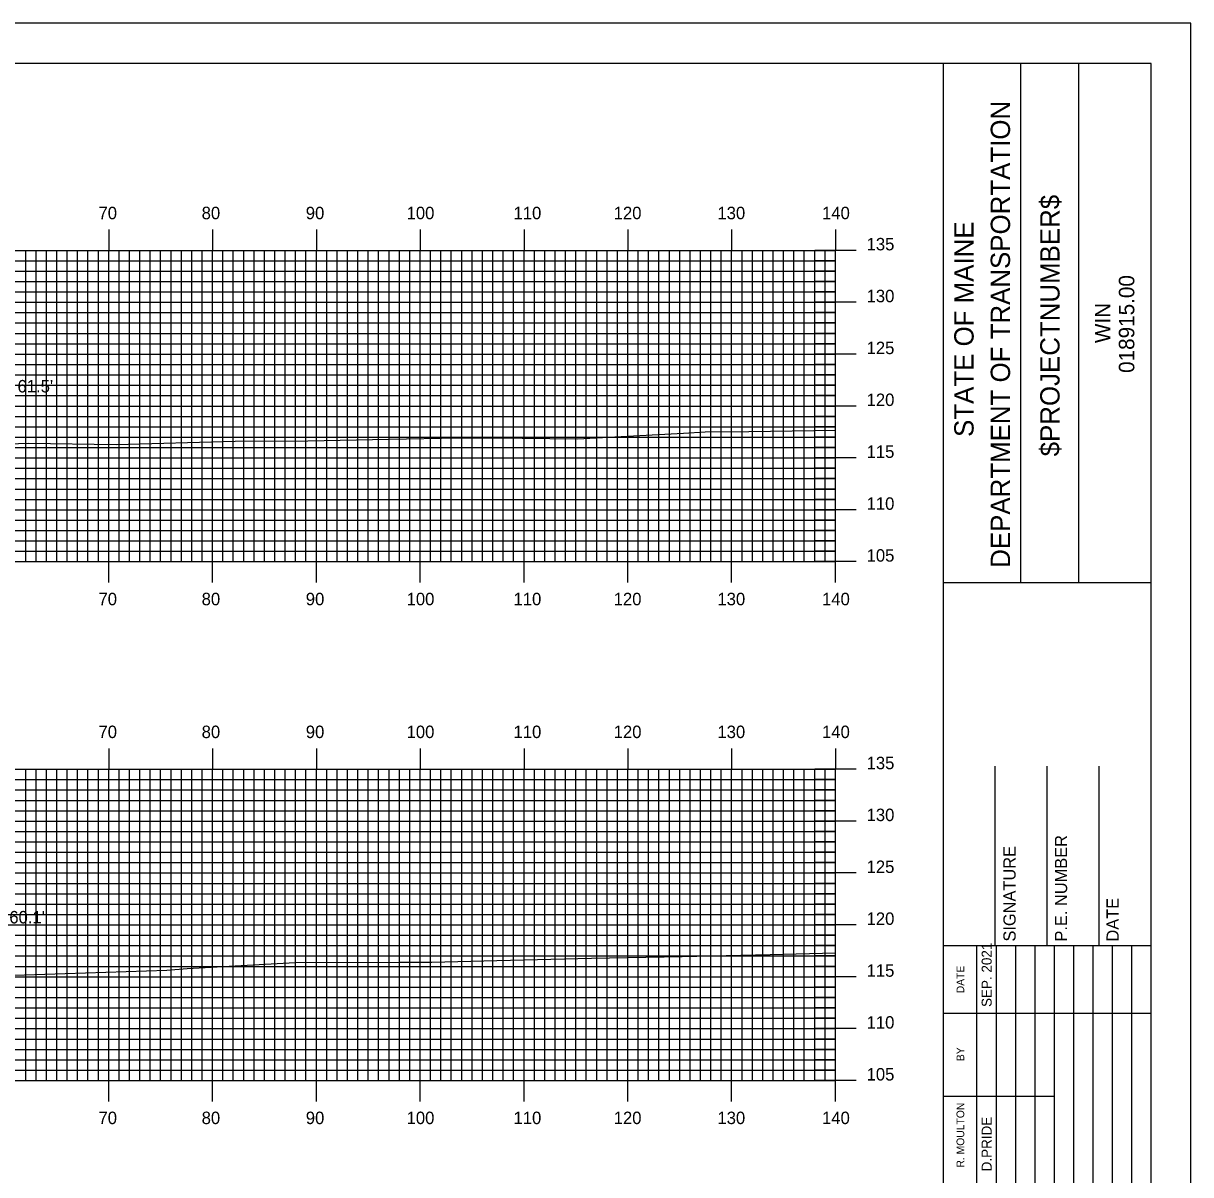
# Model space of a CAD drawing. Extents: x 1788550 to 1788893, y 442591 to 442811.
# Drawn here: x 1788777.4 to 1788889.9, y 442699.6 to 442810.5 of the extents above; entities that cross this region are included whole.
import ezdxf

# ---------------------------------------------------------------- set-up
doc = ezdxf.new("R2010")
doc.units = 0
for name, color, linetype in [('BORDER', 7, 'Continuous'), ('D_Text_Standard', 7, 'Continuous'), ('H_V ANNOTATION', 7, 'Continuous'), ('MAJOR', 7, 'Continuous'), ('MINOR', 7, 'Continuous'), ('PLOT BOUNDARY', 7, 'Continuous'), ('S_Roadway_Centerline', 7, 'Continuous')]:
    doc.layers.add(name, color=color, linetype=linetype)

msp = doc.modelspace()

# ---------------------------------------------------------------- linework, layer by layer
at = {"layer": 'BORDER'}
for p, q in [((1788866.04, 442596.67), (1788866.04, 442806.67)), ((1788873.5, 442756.66), (1788873.5, 442806.66)), ((1788879.09, 442756.66), (1788879.09, 442806.66)), ((1788866.05, 442756.65), (1788886.04, 442756.65)), ((1788871.04, 442721.67), (1788871.04, 442738.97)), ((1788876.04, 442721.67), (1788876.04, 442738.97)), ((1788881.04, 442721.67), (1788881.04, 442738.97)), ((1788866.04, 442721.67), (1788886.04, 442721.67))]:
    msp.add_line(p, q, dxfattribs=at)
msp.add_lwpolyline([(1788566.04, 442596.67), (1788886.04, 442596.67), (1788886.04, 442806.67), (1788566.04, 442806.67)], close=True, dxfattribs=at)
for points in [[(1788869.27, 442715.17), (1788869.27, 442721.67)], [(1788871.14, 442686.68), (1788871.14, 442721.67)], [(1788873, 442721.67), (1788873, 442686.68)], [(1788874.87, 442686.68), (1788874.87, 442721.67)], [(1788876.73, 442686.68), (1788876.73, 442721.67)], [(1788878.59, 442686.68), (1788878.59, 442721.67)], [(1788880.46, 442686.68), (1788880.46, 442721.67)], [(1788882.32, 442686.68), (1788882.32, 442721.67)], [(1788884.18, 442686.68), (1788884.18, 442721.67)], [(1788869.27, 442686.68), (1788869.27, 442720.26)], [(1788866.04, 442715.17), (1788886.04, 442715.17)], [(1788866.04, 442707.17), (1788869.27, 442707.17)], [(1788869.27, 442707.17), (1788876.73, 442707.17)]]:
    msp.add_lwpolyline(points, dxfattribs=at)
at = {"layer": 'MAJOR'}
for p, q in [((1788785.64, 442790.67), (1788785.64, 442788.67)), ((1788795.64, 442790.67), (1788795.64, 442788.67)), ((1788805.64, 442790.67), (1788805.64, 442788.67)), ((1788815.64, 442790.67), (1788815.64, 442788.67)), ((1788825.64, 442790.67), (1788825.64, 442788.67)), ((1788835.64, 442790.67), (1788835.64, 442788.67)), ((1788845.64, 442790.67), (1788845.64, 442788.67)), ((1788855.64, 442790.67), (1788855.64, 442788.67)), ((1788575.64, 442788.67), (1788855.64, 442788.67)), ((1788575.64, 442788.67), (1788855.64, 442788.67)), ((1788785.64, 442758.67), (1788785.64, 442788.67)), ((1788795.64, 442758.67), (1788795.64, 442788.67)), ((1788805.64, 442758.67), (1788805.64, 442788.67)), ((1788815.64, 442758.67), (1788815.64, 442788.67)), ((1788825.64, 442758.67), (1788825.64, 442788.67)), ((1788835.64, 442758.67), (1788835.64, 442788.67)), ((1788845.64, 442758.67), (1788845.64, 442788.67)), ((1788857.65, 442788.67), (1788853.64, 442788.67)), ((1788855.64, 442758.67), (1788855.64, 442788.67)), ((1788855.64, 442758.67), (1788855.64, 442788.67)), ((1788575.64, 442783.67), (1788855.64, 442783.67)), ((1788857.65, 442783.67), (1788853.64, 442783.67)), ((1788575.64, 442778.67), (1788855.64, 442778.67)), ((1788857.65, 442778.67), (1788853.64, 442778.67)), ((1788575.64, 442773.67), (1788855.64, 442773.67)), ((1788857.65, 442773.67), (1788853.64, 442773.67)), ((1788575.64, 442768.67), (1788855.64, 442768.67)), ((1788857.65, 442768.67), (1788853.64, 442768.67)), ((1788575.64, 442763.67), (1788855.64, 442763.67)), ((1788857.65, 442763.67), (1788853.64, 442763.67)), ((1788575.64, 442758.67), (1788855.64, 442758.67)), ((1788575.64, 442758.67), (1788855.64, 442758.67)), ((1788785.64, 442756.66), (1788785.64, 442758.67)), ((1788795.64, 442756.66), (1788795.64, 442758.67)), ((1788805.64, 442756.66), (1788805.64, 442758.67)), ((1788815.64, 442756.66), (1788815.64, 442758.67)), ((1788825.64, 442756.66), (1788825.64, 442758.67)), ((1788835.64, 442756.66), (1788835.64, 442758.67)), ((1788845.64, 442756.66), (1788845.64, 442758.67)), ((1788857.65, 442758.67), (1788853.64, 442758.67)), ((1788855.64, 442756.66), (1788855.64, 442758.67)), ((1788785.64, 442740.67), (1788785.64, 442738.67)), ((1788795.64, 442740.67), (1788795.64, 442738.67)), ((1788805.64, 442740.67), (1788805.64, 442738.67)), ((1788815.64, 442740.67), (1788815.64, 442738.67)), ((1788825.64, 442740.67), (1788825.64, 442738.67)), ((1788835.64, 442740.67), (1788835.64, 442738.67)), ((1788845.64, 442740.67), (1788845.64, 442738.67)), ((1788855.64, 442740.67), (1788855.64, 442738.67)), ((1788575.64, 442738.67), (1788855.64, 442738.67)), ((1788575.64, 442738.67), (1788855.64, 442738.67)), ((1788785.64, 442708.67), (1788785.64, 442738.67)), ((1788795.64, 442708.67), (1788795.64, 442738.67)), ((1788805.64, 442708.67), (1788805.64, 442738.67)), ((1788815.64, 442708.67), (1788815.64, 442738.67)), ((1788825.64, 442708.67), (1788825.64, 442738.67)), ((1788835.64, 442708.67), (1788835.64, 442738.67)), ((1788845.64, 442708.67), (1788845.64, 442738.67)), ((1788857.65, 442738.67), (1788853.64, 442738.67)), ((1788855.64, 442708.67), (1788855.64, 442738.67)), ((1788855.64, 442708.67), (1788855.64, 442738.67)), ((1788575.64, 442733.67), (1788855.64, 442733.67)), ((1788857.65, 442733.67), (1788853.64, 442733.67)), ((1788575.64, 442728.67), (1788855.64, 442728.67)), ((1788857.65, 442728.67), (1788853.64, 442728.67)), ((1788575.64, 442723.67), (1788855.64, 442723.67)), ((1788857.65, 442723.67), (1788853.64, 442723.67)), ((1788575.64, 442718.67), (1788855.64, 442718.67)), ((1788857.65, 442718.67), (1788853.64, 442718.67)), ((1788575.64, 442713.67), (1788855.64, 442713.67)), ((1788857.65, 442713.67), (1788853.64, 442713.67)), ((1788575.64, 442708.67), (1788855.64, 442708.67)), ((1788575.64, 442708.67), (1788855.64, 442708.67)), ((1788785.64, 442706.66), (1788785.64, 442708.67)), ((1788795.64, 442706.66), (1788795.64, 442708.67)), ((1788805.64, 442706.66), (1788805.64, 442708.67)), ((1788815.64, 442706.66), (1788815.64, 442708.67)), ((1788825.64, 442706.66), (1788825.64, 442708.67)), ((1788835.64, 442706.66), (1788835.64, 442708.67)), ((1788845.64, 442706.66), (1788845.64, 442708.67)), ((1788857.65, 442708.67), (1788853.64, 442708.67)), ((1788855.64, 442706.66), (1788855.64, 442708.67))]:
    msp.add_line(p, q, dxfattribs=at)
at = {"layer": 'MINOR'}
for p, q in [((1788777.64, 442758.67), (1788777.64, 442788.67)), ((1788778.64, 442758.67), (1788778.64, 442788.67)), ((1788779.64, 442758.67), (1788779.64, 442788.67)), ((1788780.64, 442758.67), (1788780.64, 442788.67)), ((1788781.64, 442758.67), (1788781.64, 442788.67)), ((1788782.64, 442758.67), (1788782.64, 442788.67)), ((1788783.64, 442758.67), (1788783.64, 442788.67)), ((1788784.64, 442758.67), (1788784.64, 442788.67)), ((1788786.64, 442758.67), (1788786.64, 442788.67)), ((1788787.64, 442758.67), (1788787.64, 442788.67)), ((1788788.64, 442758.67), (1788788.64, 442788.67)), ((1788789.64, 442758.67), (1788789.64, 442788.67)), ((1788790.64, 442758.67), (1788790.64, 442788.67)), ((1788791.64, 442758.67), (1788791.64, 442788.67)), ((1788792.64, 442758.67), (1788792.64, 442788.67)), ((1788793.64, 442758.67), (1788793.64, 442788.67)), ((1788794.64, 442758.67), (1788794.64, 442788.67)), ((1788796.64, 442758.67), (1788796.64, 442788.67)), ((1788797.64, 442758.67), (1788797.64, 442788.67)), ((1788798.64, 442758.67), (1788798.64, 442788.67)), ((1788799.64, 442758.67), (1788799.64, 442788.67)), ((1788800.64, 442758.67), (1788800.64, 442788.67)), ((1788801.64, 442758.67), (1788801.64, 442788.67)), ((1788802.64, 442758.67), (1788802.64, 442788.67)), ((1788803.64, 442758.67), (1788803.64, 442788.67)), ((1788804.64, 442758.67), (1788804.64, 442788.67)), ((1788806.64, 442758.67), (1788806.64, 442788.67)), ((1788807.64, 442758.67), (1788807.64, 442788.67)), ((1788808.64, 442758.67), (1788808.64, 442788.67)), ((1788809.64, 442758.67), (1788809.64, 442788.67)), ((1788810.64, 442758.67), (1788810.64, 442788.67)), ((1788811.64, 442758.67), (1788811.64, 442788.67)), ((1788812.64, 442758.67), (1788812.64, 442788.67)), ((1788813.64, 442758.67), (1788813.64, 442788.67)), ((1788814.64, 442758.67), (1788814.64, 442788.67)), ((1788816.64, 442758.67), (1788816.64, 442788.67)), ((1788817.64, 442758.67), (1788817.64, 442788.67)), ((1788818.64, 442758.67), (1788818.64, 442788.67)), ((1788819.64, 442758.67), (1788819.64, 442788.67)), ((1788820.64, 442758.67), (1788820.64, 442788.67)), ((1788821.64, 442758.67), (1788821.64, 442788.67)), ((1788822.64, 442758.67), (1788822.64, 442788.67)), ((1788823.64, 442758.67), (1788823.64, 442788.67)), ((1788824.64, 442758.67), (1788824.64, 442788.67)), ((1788826.64, 442758.67), (1788826.64, 442788.67)), ((1788827.64, 442758.67), (1788827.64, 442788.67)), ((1788828.64, 442758.67), (1788828.64, 442788.67)), ((1788829.64, 442758.67), (1788829.64, 442788.67)), ((1788830.64, 442758.67), (1788830.64, 442788.67)), ((1788831.64, 442758.67), (1788831.64, 442788.67)), ((1788832.64, 442758.67), (1788832.64, 442788.67)), ((1788833.64, 442758.67), (1788833.64, 442788.67)), ((1788834.64, 442758.67), (1788834.64, 442788.67)), ((1788836.64, 442758.67), (1788836.64, 442788.67)), ((1788837.64, 442758.67), (1788837.64, 442788.67)), ((1788838.64, 442758.67), (1788838.64, 442788.67)), ((1788839.64, 442758.67), (1788839.64, 442788.67)), ((1788840.64, 442758.67), (1788840.64, 442788.67)), ((1788841.64, 442758.67), (1788841.64, 442788.67)), ((1788842.64, 442758.67), (1788842.64, 442788.67)), ((1788843.64, 442758.67), (1788843.64, 442788.67)), ((1788844.64, 442758.67), (1788844.64, 442788.67)), ((1788846.64, 442758.67), (1788846.64, 442788.67)), ((1788847.64, 442758.67), (1788847.64, 442788.67)), ((1788848.64, 442758.67), (1788848.64, 442788.67)), ((1788849.64, 442758.67), (1788849.64, 442788.67)), ((1788850.64, 442758.67), (1788850.64, 442788.67)), ((1788851.64, 442758.67), (1788851.64, 442788.67)), ((1788852.64, 442758.67), (1788852.64, 442788.67)), ((1788853.64, 442758.67), (1788853.64, 442788.67)), ((1788854.64, 442758.67), (1788854.64, 442788.67)), ((1788575.64, 442787.67), (1788855.64, 442787.67)), ((1788855.64, 442787.67), (1788853.64, 442787.67)), ((1788575.64, 442786.67), (1788855.64, 442786.67)), ((1788855.64, 442786.67), (1788853.64, 442786.67)), ((1788575.64, 442785.67), (1788855.64, 442785.67)), ((1788855.64, 442785.67), (1788853.64, 442785.67)), ((1788575.64, 442784.67), (1788855.64, 442784.67)), ((1788855.64, 442784.67), (1788853.64, 442784.67)), ((1788575.64, 442782.67), (1788855.64, 442782.67)), ((1788855.64, 442782.67), (1788853.64, 442782.67)), ((1788575.64, 442781.67), (1788855.64, 442781.67)), ((1788855.64, 442781.67), (1788853.64, 442781.67)), ((1788575.64, 442780.67), (1788855.64, 442780.67)), ((1788575.64, 442779.67), (1788855.64, 442779.67)), ((1788855.64, 442780.67), (1788853.64, 442780.67)), ((1788855.64, 442779.67), (1788853.64, 442779.67)), ((1788575.64, 442777.67), (1788855.64, 442777.67)), ((1788855.64, 442777.67), (1788853.64, 442777.67)), ((1788575.64, 442776.67), (1788855.64, 442776.67)), ((1788855.64, 442776.67), (1788853.64, 442776.67)), ((1788575.64, 442775.67), (1788855.64, 442775.67)), ((1788855.64, 442775.67), (1788853.64, 442775.67)), ((1788575.64, 442774.67), (1788855.64, 442774.67)), ((1788855.64, 442774.67), (1788853.64, 442774.67)), ((1788575.64, 442772.67), (1788855.64, 442772.67)), ((1788855.64, 442772.67), (1788853.64, 442772.67)), ((1788575.64, 442771.67), (1788855.64, 442771.67)), ((1788575.64, 442770.67), (1788855.64, 442770.67)), ((1788855.64, 442771.67), (1788853.64, 442771.67)), ((1788855.64, 442770.67), (1788853.64, 442770.67)), ((1788575.64, 442769.67), (1788855.64, 442769.67)), ((1788855.64, 442769.67), (1788853.64, 442769.67)), ((1788575.64, 442767.67), (1788855.64, 442767.67)), ((1788855.64, 442767.67), (1788853.64, 442767.67)), ((1788575.64, 442766.67), (1788855.64, 442766.67)), ((1788855.64, 442766.67), (1788853.64, 442766.67)), ((1788575.64, 442765.67), (1788855.64, 442765.67)), ((1788855.64, 442765.67), (1788853.64, 442765.67)), ((1788575.64, 442764.67), (1788855.64, 442764.67)), ((1788855.64, 442764.67), (1788853.64, 442764.67)), ((1788575.64, 442762.67), (1788855.64, 442762.67)), ((1788575.64, 442761.67), (1788855.64, 442761.67)), ((1788855.64, 442762.67), (1788853.64, 442762.67)), ((1788855.64, 442761.67), (1788853.64, 442761.67)), ((1788575.64, 442760.67), (1788855.64, 442760.67)), ((1788855.64, 442760.67), (1788853.64, 442760.67)), ((1788575.64, 442759.67), (1788855.64, 442759.67)), ((1788855.64, 442759.67), (1788853.64, 442759.67)), ((1788777.64, 442708.67), (1788777.64, 442738.67)), ((1788778.64, 442708.67), (1788778.64, 442738.67)), ((1788779.64, 442708.67), (1788779.64, 442738.67)), ((1788780.64, 442708.67), (1788780.64, 442738.67)), ((1788781.64, 442708.67), (1788781.64, 442738.67)), ((1788782.64, 442708.67), (1788782.64, 442738.67)), ((1788783.64, 442708.67), (1788783.64, 442738.67)), ((1788784.64, 442708.67), (1788784.64, 442738.67)), ((1788786.64, 442708.67), (1788786.64, 442738.67)), ((1788787.64, 442708.67), (1788787.64, 442738.67)), ((1788788.64, 442708.67), (1788788.64, 442738.67)), ((1788789.64, 442708.67), (1788789.64, 442738.67)), ((1788790.64, 442708.67), (1788790.64, 442738.67)), ((1788791.64, 442708.67), (1788791.64, 442738.67)), ((1788792.64, 442708.67), (1788792.64, 442738.67)), ((1788793.64, 442708.67), (1788793.64, 442738.67)), ((1788794.64, 442708.67), (1788794.64, 442738.67)), ((1788796.64, 442708.67), (1788796.64, 442738.67)), ((1788797.64, 442708.67), (1788797.64, 442738.67)), ((1788798.64, 442708.67), (1788798.64, 442738.67)), ((1788799.64, 442708.67), (1788799.64, 442738.67)), ((1788800.64, 442708.67), (1788800.64, 442738.67)), ((1788801.64, 442708.67), (1788801.64, 442738.67)), ((1788802.64, 442708.67), (1788802.64, 442738.67)), ((1788803.64, 442708.67), (1788803.64, 442738.67)), ((1788804.64, 442708.67), (1788804.64, 442738.67)), ((1788806.64, 442708.67), (1788806.64, 442738.67)), ((1788807.64, 442708.67), (1788807.64, 442738.67)), ((1788808.64, 442708.67), (1788808.64, 442738.67)), ((1788809.64, 442708.67), (1788809.64, 442738.67)), ((1788810.64, 442708.67), (1788810.64, 442738.67)), ((1788811.64, 442708.67), (1788811.64, 442738.67)), ((1788812.64, 442708.67), (1788812.64, 442738.67)), ((1788813.64, 442708.67), (1788813.64, 442738.67)), ((1788814.64, 442708.67), (1788814.64, 442738.67)), ((1788816.64, 442708.67), (1788816.64, 442738.67)), ((1788817.64, 442708.67), (1788817.64, 442738.67)), ((1788818.64, 442708.67), (1788818.64, 442738.67)), ((1788819.64, 442708.67), (1788819.64, 442738.67)), ((1788820.64, 442708.67), (1788820.64, 442738.67)), ((1788821.64, 442708.67), (1788821.64, 442738.67)), ((1788822.64, 442708.67), (1788822.64, 442738.67)), ((1788823.64, 442708.67), (1788823.64, 442738.67)), ((1788824.64, 442708.67), (1788824.64, 442738.67)), ((1788826.64, 442708.67), (1788826.64, 442738.67)), ((1788827.64, 442708.67), (1788827.64, 442738.67)), ((1788828.64, 442708.67), (1788828.64, 442738.67)), ((1788829.64, 442708.67), (1788829.64, 442738.67)), ((1788830.64, 442708.67), (1788830.64, 442738.67)), ((1788831.64, 442708.67), (1788831.64, 442738.67)), ((1788832.64, 442708.67), (1788832.64, 442738.67)), ((1788833.64, 442708.67), (1788833.64, 442738.67)), ((1788834.64, 442708.67), (1788834.64, 442738.67)), ((1788836.64, 442708.67), (1788836.64, 442738.67)), ((1788837.64, 442708.67), (1788837.64, 442738.67)), ((1788838.64, 442708.67), (1788838.64, 442738.67)), ((1788839.64, 442708.67), (1788839.64, 442738.67)), ((1788840.64, 442708.67), (1788840.64, 442738.67)), ((1788841.64, 442708.67), (1788841.64, 442738.67)), ((1788842.64, 442708.67), (1788842.64, 442738.67)), ((1788843.64, 442708.67), (1788843.64, 442738.67)), ((1788844.64, 442708.67), (1788844.64, 442738.67)), ((1788846.64, 442708.67), (1788846.64, 442738.67)), ((1788847.64, 442708.67), (1788847.64, 442738.67)), ((1788848.64, 442708.67), (1788848.64, 442738.67)), ((1788849.64, 442708.67), (1788849.64, 442738.67)), ((1788850.64, 442708.67), (1788850.64, 442738.67)), ((1788851.64, 442708.67), (1788851.64, 442738.67)), ((1788852.64, 442708.67), (1788852.64, 442738.67)), ((1788853.64, 442708.67), (1788853.64, 442738.67)), ((1788854.64, 442708.67), (1788854.64, 442738.67)), ((1788575.64, 442737.67), (1788855.64, 442737.67)), ((1788855.64, 442737.67), (1788853.64, 442737.67)), ((1788575.64, 442736.67), (1788855.64, 442736.67)), ((1788855.64, 442736.67), (1788853.64, 442736.67)), ((1788575.64, 442735.67), (1788855.64, 442735.67)), ((1788575.64, 442734.67), (1788855.64, 442734.67)), ((1788855.64, 442735.67), (1788853.64, 442735.67)), ((1788855.64, 442734.67), (1788853.64, 442734.67)), ((1788575.64, 442732.67), (1788855.64, 442732.67)), ((1788855.64, 442732.67), (1788853.64, 442732.67)), ((1788575.64, 442731.67), (1788855.64, 442731.67)), ((1788855.64, 442731.67), (1788853.64, 442731.67)), ((1788575.64, 442730.67), (1788855.64, 442730.67)), ((1788855.64, 442730.67), (1788853.64, 442730.67)), ((1788575.64, 442729.67), (1788855.64, 442729.67)), ((1788855.64, 442729.67), (1788853.64, 442729.67)), ((1788575.64, 442727.67), (1788855.64, 442727.67)), ((1788855.64, 442727.67), (1788853.64, 442727.67)), ((1788575.64, 442726.67), (1788855.64, 442726.67)), ((1788575.64, 442725.67), (1788855.64, 442725.67)), ((1788855.64, 442726.67), (1788853.64, 442726.67)), ((1788855.64, 442725.67), (1788853.64, 442725.67)), ((1788575.64, 442724.67), (1788855.64, 442724.67)), ((1788855.64, 442724.67), (1788853.64, 442724.67)), ((1788575.64, 442722.67), (1788855.64, 442722.67)), ((1788855.64, 442722.67), (1788853.64, 442722.67)), ((1788575.64, 442721.67), (1788855.64, 442721.67)), ((1788855.64, 442721.67), (1788853.64, 442721.67)), ((1788575.64, 442720.67), (1788855.64, 442720.67)), ((1788855.64, 442720.67), (1788853.64, 442720.67)), ((1788575.64, 442719.67), (1788855.64, 442719.67)), ((1788855.64, 442719.67), (1788853.64, 442719.67)), ((1788575.64, 442717.67), (1788855.64, 442717.67)), ((1788575.64, 442716.67), (1788855.64, 442716.67)), ((1788855.64, 442717.67), (1788853.64, 442717.67)), ((1788855.64, 442716.67), (1788853.64, 442716.67)), ((1788575.64, 442715.67), (1788855.64, 442715.67)), ((1788855.64, 442715.67), (1788853.64, 442715.67)), ((1788575.64, 442714.67), (1788855.64, 442714.67)), ((1788855.64, 442714.67), (1788853.64, 442714.67)), ((1788575.64, 442712.67), (1788855.64, 442712.67)), ((1788855.64, 442712.67), (1788853.64, 442712.67)), ((1788575.64, 442711.67), (1788855.64, 442711.67)), ((1788855.64, 442711.67), (1788853.64, 442711.67)), ((1788575.64, 442710.67), (1788855.64, 442710.67)), ((1788855.64, 442710.67), (1788853.64, 442710.67)), ((1788575.64, 442709.67), (1788855.64, 442709.67)), ((1788855.64, 442709.67), (1788853.64, 442709.67))]:
    msp.add_line(p, q, dxfattribs=at)
at = {"layer": 'PLOT BOUNDARY'}
msp.add_lwpolyline([(1788549.86, 442590.55), (1788889.86, 442590.55), (1788889.86, 442810.55), (1788549.86, 442810.55)], close=True, dxfattribs=at)
at = {"layer": 'S_Roadway_Centerline'}
for points in [[(1788767.17, 442769.73), (1788777.92, 442770.08), (1788786.34, 442769.96), (1788797.83, 442770.27), (1788804.81, 442770.3), (1788812.61, 442770.48), (1788819.41, 442770.6), (1788822.8, 442770.59), (1788830.79, 442770.52), (1788841, 442771.06), (1788843.09, 442771.18), (1788847.3, 442771.22), (1788855.63, 442771.34), (1788855.64, 442771.34)], [(1788775.56, 442718.79), (1788791.23, 442719.32), (1788793.2, 442719.46), (1788803.59, 442720.04), (1788813.72, 442720.08), (1788816.75, 442720.09), (1788823.02, 442720.22), (1788832.15, 442720.47), (1788840.88, 442720.63), (1788849.34, 442720.82), (1788855.64, 442720.99)]]:
    msp.add_lwpolyline(points, dxfattribs=at)

# ---------------------------------------------------------------- texts
at = {"layer": 'BORDER'}
for s, height, p in [('DEPARTMENT OF TRANSPORTATION', 1.8635, (1788872.46, 442758.08)), ('$PROJECTNUMBER$', 1.8635, (1788877.23, 442768.82)), ('STATE OF MAINE', 1.8635, (1788868.95, 442770.69)), ('018915.00', 1.491, (1788884.43, 442776.86)), ('WIN', 1.491, (1788882.12, 442779.73)), ('SIGNATURE', 1.181, (1788873, 442722.06)), ('P.E. NUMBER', 1.1811, (1788877.96, 442722.06)), ('DATE', 1.181, (1788882.93, 442722.06)), ('SEP. 2021', 0.969, (1788870.69, 442715.76)), ('DATE', 0.743, (1788868.05, 442717.08)), ('BY', 0.743, (1788868.05, 442710.54)), ('R. MOULTON', 0.745, (1788868.05, 442700.28)), ('D.PRIDE', 0.969, (1788870.69, 442699.92))]:
    msp.add_text(s, height=height, rotation=90, dxfattribs=at).set_placement(p)
at = {"layer": 'D_Text_Standard'}
for s, p in [("61.5'", (1788776.85, 442774.98)), ("60.1'", (1788776.06, 442723.81))]:
    msp.add_text(s, height=1.2, dxfattribs=at).set_placement(p)
at = {"layer": 'H_V ANNOTATION'}
for s, p in [('70', (1788784.65, 442791.67)), ('80', (1788794.59, 442791.67)), ('90', (1788804.62, 442791.67)), ('100', (1788814.33, 442791.67)), ('110', (1788824.63, 442791.67)), ('120', (1788834.28, 442791.67)), ('130', (1788844.27, 442791.67)), ('140', (1788854.35, 442791.67)), ('135', (1788858.64, 442788.67)), ('130', (1788858.64, 442783.67)), ('125', (1788858.64, 442778.67)), ('120', (1788858.64, 442773.67)), ('115', (1788858.64, 442768.67)), ('110', (1788858.64, 442763.67)), ('105', (1788858.64, 442758.67)), ('70', (1788784.65, 442754.47)), ('80', (1788794.59, 442754.47)), ('90', (1788804.62, 442754.47)), ('100', (1788814.33, 442754.47)), ('110', (1788824.63, 442754.47)), ('120', (1788834.28, 442754.47)), ('130', (1788844.27, 442754.47)), ('140', (1788854.35, 442754.47)), ('70', (1788784.65, 442741.67)), ('80', (1788794.59, 442741.67)), ('90', (1788804.62, 442741.67)), ('100', (1788814.33, 442741.67)), ('110', (1788824.63, 442741.67)), ('120', (1788834.28, 442741.67)), ('130', (1788844.27, 442741.67)), ('140', (1788854.35, 442741.67)), ('135', (1788858.64, 442738.67)), ('130', (1788858.64, 442733.67)), ('125', (1788858.64, 442728.67)), ('120', (1788858.64, 442723.67)), ('115', (1788858.64, 442718.67)), ('110', (1788858.64, 442713.67)), ('105', (1788858.64, 442708.67)), ('70', (1788784.65, 442704.47)), ('80', (1788794.59, 442704.47)), ('90', (1788804.62, 442704.47)), ('100', (1788814.33, 442704.47)), ('110', (1788824.63, 442704.47)), ('120', (1788834.28, 442704.47)), ('130', (1788844.27, 442704.47)), ('140', (1788854.35, 442704.47))]:
    msp.add_text(s, height=1.2, dxfattribs=at).set_placement(p)

doc.saveas('drawing.dxf')
